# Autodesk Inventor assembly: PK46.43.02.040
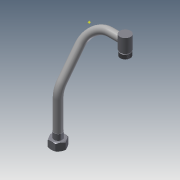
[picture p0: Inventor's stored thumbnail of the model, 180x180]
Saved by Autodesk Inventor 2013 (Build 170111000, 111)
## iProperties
Shininess: 64.0
Length Units: 11269
Angle Units: 11279
Time Units: 11290
Mass Units: 11283
Length Display Precision: 3
Angle Display Precision: 2
Compacted: True
Created: 2004-12
Part Number: PK46.43.02.040
Document SubType Name: Assembly
Designer: ELarisa
Manufacturer: Standard
Standards Organization: Custom
Density: 0.0
Volumn: 0.0
Area: 0.0
PropertySet Name: Model Information
Control State: 0
Master: False
Checked Out: False
Checked Out Date: 2008-10-09
Last Check In Date: 2008-10-09
Author: ELarisa
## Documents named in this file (5)
- D:\FrontLoaderVault\Data\Assy, Chassis, Front\PK46.43.02.040.iam
- D:\FrontLoaderVault\Data\Assy, Chassis, Front\PK46.43.02.017.ipt
- D:\FrontLoaderVault\Data\Assy, Chassis, Front\027.07.01.019-01.ipt
- D:\FrontLoaderVault\Data\Assy, Chassis, Front\027.08.00.125.ipt
- D:\FrontLoaderVault\Data\Assy, Chassis, Front\PK46.43.02.019.ipt
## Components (4 placed, 4 different names)
1. PK46.43.02.017:1 — Insert:4, Insert:5, Angle:1
2. 027.07.01.019-01:1 — Insert:3, Insert:4
3. 027.08.00.125:1 — Insert:3
4. PK46.43.02.019:1 — Insert:5, Angle:1
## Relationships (4: Insert 3, Angle 1)
- Insert:3: 027.07.01.019-01:1 ↔ 027.08.00.125:1
- Insert:4: PK46.43.02.017:1 ↔ 027.07.01.019-01:1
- Insert:5: PK46.43.02.017:1 ↔ PK46.43.02.019:1
- Angle:1: PK46.43.02.017:1 ↔ PK46.43.02.019:1
